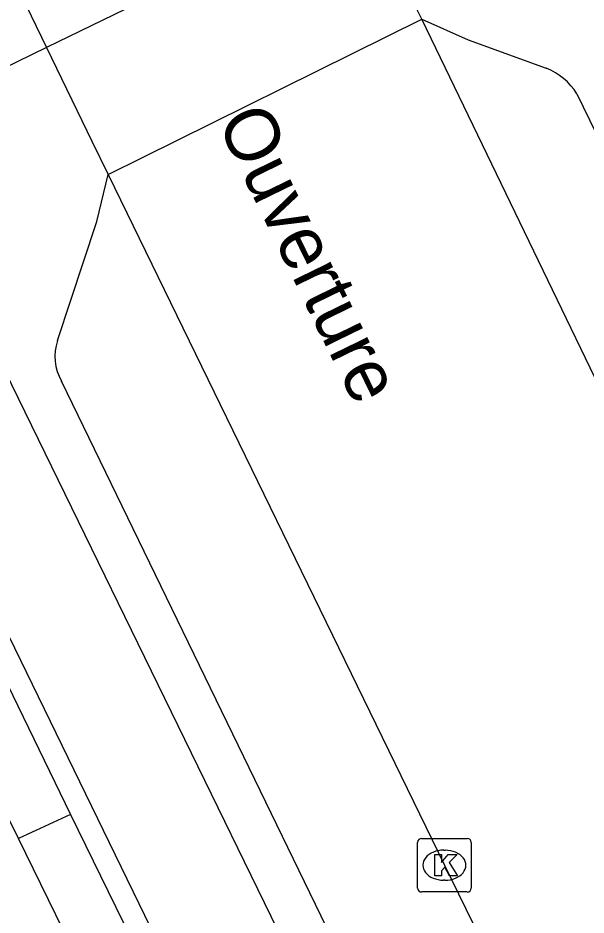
# Model space of a CAD drawing. Extents: x 160457 to 162082, y 388340 to 389736.
# Drawn here: x 160971.58 to 160982.18, y 388840.01 to 388856.74 of the extents above; entities that cross this region are included whole.
import ezdxf

# ---------------------------------------------------------------- set-up
doc = ezdxf.new("R2010")
doc.units = 0
for name, color, linetype in [('IMGEO_Fietspad_gesloten', 7, 'Continuous'), ('IMGEO_Kolk', 7, 'Continuous'), ('IMGEO_Openbare_ruimte_label', 7, 'Continuous'), ('IMGEO_Parkeervlak_open', 7, 'Continuous'), ('IMGEO_Rijbaan_lokaal_gesloten', 7, 'Continuous'), ('IMGEO_Voetpad_gesloten', 7, 'Continuous'), ('IMGEO_Voetpad_open', 7, 'Continuous')]:
    doc.layers.add(name, color=color, linetype=linetype)

msp = doc.modelspace()

# ---------------------------------------------------------------- linework, layer by layer
at = {"layer": 'IMGEO_Fietspad_gesloten'}
for points in [[(160981.143, 388830.068), (160969.977, 388852.944), (160969.108, 388854.725)], [(160967.226, 388853.81), (160968.207, 388851.798), (160979.24, 388829.116)]]:
    msp.add_lwpolyline(points, dxfattribs=at)
at = {"layer": 'IMGEO_Kolk'}
for p, q in [((160979.034, 388840.513), (160979.034, 388841.365)), ((160979.109, 388841.439), (160979.961, 388841.439)), ((160980.035, 388841.365), (160980.035, 388840.513)), ((160979.522, 388841.219), (160979.547, 388841.219)), ((160979.545, 388840.659), (160979.52, 388840.659)), ((160979.961, 388840.439), (160979.109, 388840.439))]:
    msp.add_line(p, q, dxfattribs=at)
for points in [[(160979.034, 388840.513), (160979.034, 388841.365)], [(160979.109, 388841.439), (160979.961, 388841.439)], [(160980.035, 388841.365), (160980.035, 388840.513)], [(160979.355, 388841.139), (160979.478, 388841.139), (160979.478, 388840.988), (160979.608, 388841.139), (160979.772, 388841.139), (160979.626, 388840.988), (160979.779, 388840.739), (160979.627, 388840.739), (160979.542, 388840.903), (160979.478, 388840.836), (160979.478, 388840.739), (160979.355, 388840.739), (160979.355, 388841.139)], [(160979.961, 388840.439), (160979.109, 388840.439)]]:
    msp.add_lwpolyline(points, dxfattribs=at)
for centre, start, end in [((160979.111, 388841.363), 91.552, 178.448), ((160979.111, 388841.363), 91.552, 178.448), ((160979.959, 388841.363), 1.552, 88.448), ((160979.959, 388841.363), 1.552, 88.448), ((160979.111, 388840.515), 181.552, 268.448), ((160979.111, 388840.515), 181.552, 268.448), ((160979.959, 388840.515), 271.552, 358.448), ((160979.959, 388840.515), 271.552, 358.448)]:
    msp.add_arc(centre, 0.0765, start, end, dxfattribs=at)
for centre, major_axis, ratio, start_param, end_param in [((160979.521, 388840.939), (-0.387, 0.002), 0.722429, 4.712389, 7.853982), ((160979.546, 388840.939), (-0.39, 0.002), 0.717154, 1.570796, 4.712389)]:
    msp.add_ellipse(centre, major_axis=major_axis, ratio=ratio, start_param=start_param, end_param=end_param, dxfattribs=at)
at = {"layer": 'IMGEO_Parkeervlak_open'}
for points in [[(160979.112, 388856.719), (160979.981, 388856.335), (160981.435, 388855.804)], [(160982.005, 388855.326), (160991.785, 388835.246)], [(160972.324, 388850.724), (160973.057, 388852.946), (160973.268, 388853.82)], [(160981.87, 388830.442), (160972.397, 388849.97)]]:
    msp.add_lwpolyline(points, dxfattribs=at)
for centre, radius, start, end in [((160980.984, 388854.688), 1.204, 32.0208, 68.013), ((160973.17, 388850.425), 0.897, 160.5552, 210.5048)]:
    msp.add_arc(centre, radius, start, end, dxfattribs=at)
at = {"layer": 'IMGEO_Rijbaan_lokaal_gesloten'}
for points in [[(160977.973, 388859.04), (160972.117, 388856.19)], [(160979.112, 388856.719), (160978.929, 388857.097), (160978.818, 388857.327), (160977.973, 388859.04)], [(160973.268, 388853.82), (160979.112, 388856.719)], [(161002.577, 388808.494), (161000, 388813.8), (160993.848, 388826.468), (160984.865, 388844.805), (160979.112, 388856.719)], [(160972.117, 388856.19), (160972.964, 388854.444), (160973.268, 388853.82)], [(160973.268, 388853.82), (160979.536, 388840.94), (160987.843, 388823.92), (160995.313, 388808.673), (160996.539, 388806.059)]]:
    msp.add_lwpolyline(points, dxfattribs=at)
at = {"layer": 'IMGEO_Voetpad_gesloten'}
msp.add_lwpolyline([(160970.682, 388859.148), (160972.117, 388856.19)], dxfattribs=at)
at = {"layer": 'IMGEO_Voetpad_open'}
for points in [[(160972.117, 388856.19), (160969.108, 388854.725)], [(160967.853, 388851.597), (160972.565, 388841.887)], [(160971.593, 388841.435), (160966.856, 388851.087)], [(160972.565, 388841.887), (160971.593, 388841.435)], [(160972.565, 388841.887), (160978.889, 388828.943), (160979.24, 388829.116)], [(160979.736, 388828.183), (160978.413, 388827.493), (160971.593, 388841.435)]]:
    msp.add_lwpolyline(points, dxfattribs=at)

# ---------------------------------------------------------------- texts
at = {"layer": 'IMGEO_Openbare_ruimte_label'}
msp.add_text('Ouverture', height=1, rotation=295.9757, dxfattribs=at).set_placement((160975.282, 388854.811))

doc.saveas('drawing.dxf')
